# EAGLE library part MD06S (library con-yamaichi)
YAMAICHI CONNECTOR
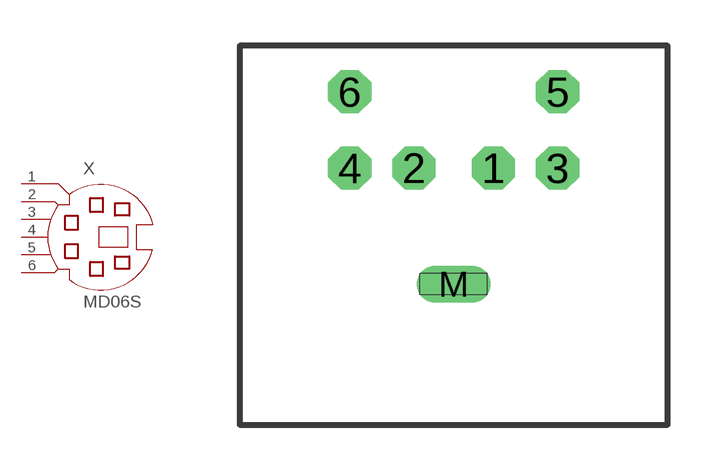
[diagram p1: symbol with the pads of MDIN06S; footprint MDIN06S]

Designator prefix X

## MD06S (OC_FARNELL: unknown; OC_NEWARK: unknown)  [MDIN06S]
1  1  pas
2  2  pas
3  3  pas
4  4  pas
5  5  pas
6  6  pas

## Footprint MDIN06S (pad centres in mm)
Mini Din YAMAICHI CONNECTOR
drill 0.9 octagon: 1 1.3,8.5; 2 -1.3,8.5; 3 3.4,8.5; 4 -3.4,8.5; 5 3.4,11; 6 -3.4,11
drill 0.7 long: M 0,4.7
